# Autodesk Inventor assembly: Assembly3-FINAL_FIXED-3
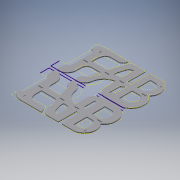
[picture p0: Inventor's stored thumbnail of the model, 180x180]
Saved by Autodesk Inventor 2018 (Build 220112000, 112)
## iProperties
Created: 2018-03
Part Number: Assembly3-FINAL_FIXED-3
Document SubType Name: Assembly
Designer: katin
Author: katin
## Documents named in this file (3)
- C:\Users\katin\Documents\FabAcademy2018\+MODEL-FILES\Week 7\+CNC+\Assembly3-FINAL_FIXED-3.iam
- C:\Users\katin\Documents\FabAcademy2018\+MODEL-FILES\Week 7\+CNC+\w8-FAB-shelf-holes-10-Final++from9.ipt
- C:\Users\katin\Documents\FabAcademy2018\+MODEL-FILES\Week 7\+CNC+\w8-FAB-shelf-holes-9-Final++.ipt
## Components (2 placed, 2 different names)
1. w8-FAB-shelf-holes-10-Final++from9:1 — Flush:1, Mate:2
2. w8-FAB-shelf-holes-9-Final++:1 — Flush:1, Mate:2
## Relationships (2: Flush 1, Mate 1)
- Flush:1: w8-FAB-shelf-holes-10-Final++from9:1 ↔ w8-FAB-shelf-holes-9-Final++:1
- Mate:2: w8-FAB-shelf-holes-10-Final++from9:1 ↔ w8-FAB-shelf-holes-9-Final++:1
